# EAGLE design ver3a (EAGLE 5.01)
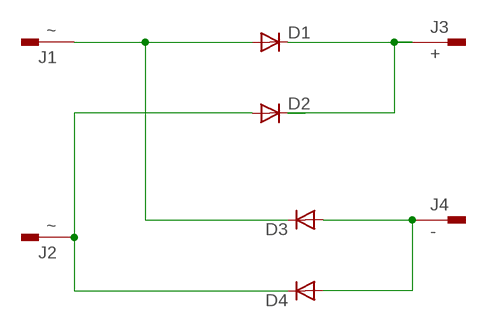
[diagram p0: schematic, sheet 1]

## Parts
D1  DIODE-SMC  [SMC]
D2  DIODE-SMC  [SMC]
D3  DIODE-SMC  [SMC]
D4  DIODE-SMC  [SMC]
J1  ~  PIN2F061.200  [F061.200]
J2  ~  PIN2F061.200  [F061.200]
J3  +  PIN2F061.200  [F061.200]
J4  -  PIN2F061.200  [F061.200]

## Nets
N$2: D1.A D3.C J1.1A
N$4: D3.A D4.A J4.1A
N$6: D1.C D2.C J3.1A
N$10: D2.A D4.C J2.1A
Unconnected: J1.1B(1.1) J2.1B(1.1) J3.1B(1.1) J4.1B(1.1)

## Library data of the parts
D1-D4 = diode:DIODE-: DIODE
J1-J4 = con-faston:PIN2: Flachstecker Typ Tyco/Electronics/AMP TAB, FASTON

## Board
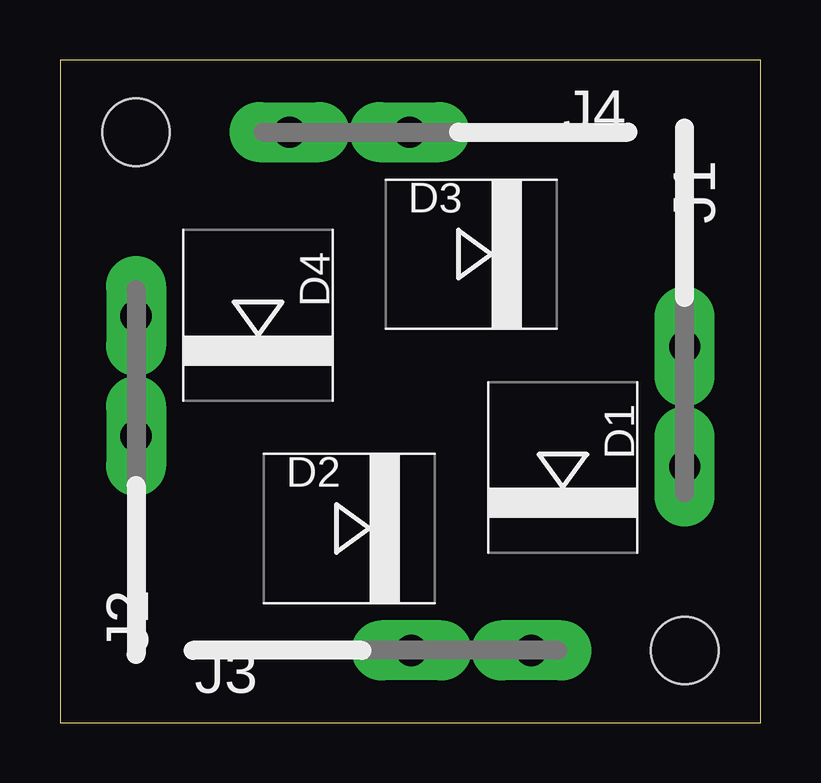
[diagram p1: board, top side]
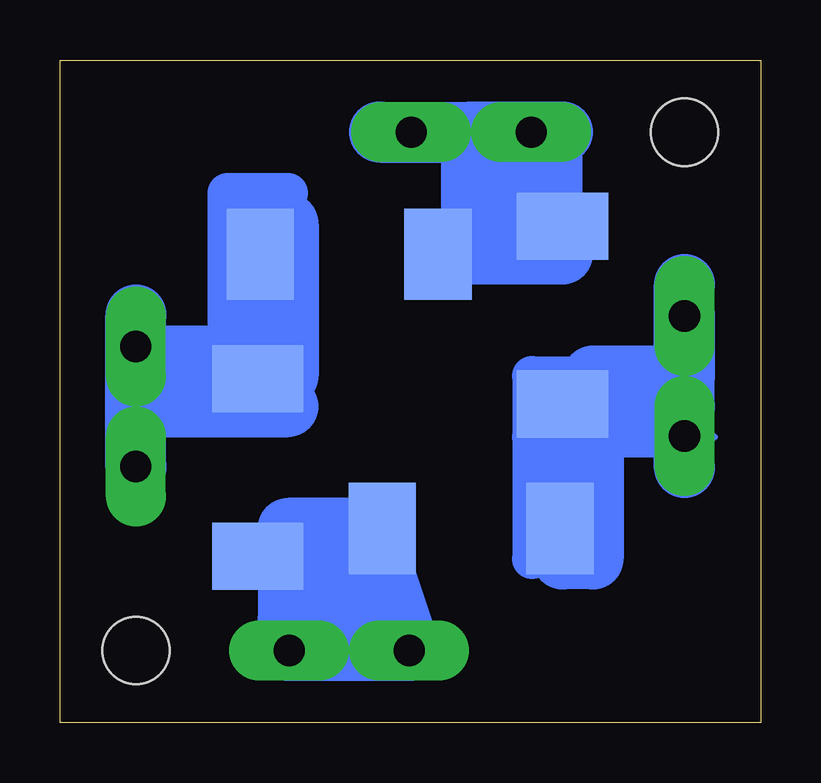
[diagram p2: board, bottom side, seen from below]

Size 29.19 x 27.61 mm. Coordinates in mm from the lower left corner, seen from the top.
Outline: 0,0 29.19,0 29.19,27.61 0,27.61 0,0
Copper layers (1*16): Top 0.035mm / dielectric 1.5mm / Bottom 0.035mm
Design rules "default": minimum track width 10mil, minimum drill 24mil, track to track 8mil, track to pad 8mil, pad to pad 8mil, via to via 8mil, smd to smd 8mil, copper to edge 40mil, drill to drill 8mil, minimum pad ring 10mil, minimum via ring 8mil, stop-mask expansion 4mil, vias tented up to drill 0mil, thermal gap 10mil
Holes 2.8 mm at 3.17,24.6 26.03,3.01

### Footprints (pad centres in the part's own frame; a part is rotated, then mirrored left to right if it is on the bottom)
SMC = smd 2.8 x 3.8 bottom: A 3.7,0; C -3.7,0
F061.200 = drill 1.3 pad 2.5 long: 1A -2.5,0; 1B 2.5,0

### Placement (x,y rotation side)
D1  20.95,10.63 90 top
D2  12.06,8.09 180 top
D3  17.14,19.52 180 top
D4  8.25,16.98 90 top
J1  26.03,13.17 90 top
J2  3.17,14.44 270 top
J3  17.14,3.01 180 top
J4  12.06,24.6 0 top

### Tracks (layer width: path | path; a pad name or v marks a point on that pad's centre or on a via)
N$1
  Bottom 2.54: 8.25,19.52 13.33,19.52
N$2
  Bottom 0.254: 20.95,18.25 D3.C | D1.A 22.22,13.17
  Bottom 2.54: D1.A 20.95,18.25 | 22.22,13.17 26.03,13.17 | 26.03,10.63 J1.1A 26.03,13.17 | 26.03,13.17 26.03,16.98 | 26.03,13.17 19.68,13.17
N$4
  Bottom 0.254: 9.52,20.79 D4.A 9.52,22.06 | 12.06,20.79 D3.A
  Bottom 2.54: J4.1A 9.52,24.6 9.52,22.06 | 9.52,20.79 12.06,20.79
N$6
  Bottom 0.254: 19.68,8.09 D1.C
  Bottom 1.676: 19.68,3.01 J3.1A
  Bottom 2.54: D2.C 19.68,8.09 | D1.C 17.14,5.55 17.14,4.28 18.41,3.01 | 19.68,3.01 18.41,3.01 | 18.41,3.01 15.87,3.01 | 15.87,3.01 17.14,6.82 15.87,6.82 | 15.87,6.82 15.87,3.01 | 15.87,3.01 14.6,3.01 15.87,6.82
N$7
  Bottom 2.54: 19.68,6.82 19.68,4.28
N$9
  Bottom 1.676: 8.25,20.79 8.25,24.6
  Bottom 2.54: 8.25,24.6 12.06,24.6 | 15.87,24.6 12.06,24.6 | 12.06,24.6 12.06,20.79
N$10
  Bottom 0.254: 1.9,11.9 3.17,13.17 J2.1A 3.17,16.98 | 8.25,9.36 D2.A | 6.98,14.44 D4.C
  Bottom 1.676: 9.52,11.9 9.52,14.44 3.17,14.44 | 9.52,11.9 9.52,6.82 | 9.52,11.9 3.17,11.9 | 3.17,13.17 6.98,13.17
  Bottom 2.54: 3.17,10.63 3.17,11.9 3.17,13.17 3.17,14.44 | 3.17,14.44 3.17,18.25 | D4.C 8.25,13.17 | 8.25,13.17 8.25,9.36 | 3.17,16.98 3.17,14.44 | 3.17,14.44 6.98,14.44 6.98,13.17 6.98,6.82 8.25,6.82 8.25,13.17
N$11
  Bottom 1.676: 19.68,22.06 22.22,22.06 22.22,15.71 | 22.22,15.71 22.22,14.44 | 22.22,15.71 26.03,15.71
  Bottom 2.54: 19.68,20.79 19.68,14.44 22.22,14.44 26.03,14.44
